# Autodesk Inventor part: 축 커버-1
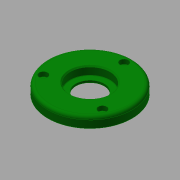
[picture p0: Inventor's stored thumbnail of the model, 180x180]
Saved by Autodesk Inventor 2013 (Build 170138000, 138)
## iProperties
Created: 2015-10
Part Number: 축 커버-1
Document SubType Name: Modeling
Designer: mdu
Density: 7.86 g/cm^3
Material: 강철, 연강
Mass: 324.903 g
Surface Area: 132.124 cm^2
Volume: 41.3362 cm^3
Author: mdu
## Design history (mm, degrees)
sketch "스케치1"
  geometry: C1 r 40 at (0, 0) reference; C2 r 26 at (0, 0) reference; 1 further point
  node "참조1"
  node "참조2"
extrude "돌출1" new body sketch "스케치1" distance "d0" = 10; taper "d1" = 0 deg
extrude "돌출2" join sketch "스케치1" distance "d2" = 3; taper "d3" = 0 deg
hole "구멍1" diameter "d6" = 27; stored, may be unused: countersink angle "d10" = 90 deg, drill point angle "d12" = 118 deg; dims "d4" = 10, "d5" = 10, "d7" = 6, "d8" = 38, "d9" = 8, "d11" = 8
sketch "스케치2"
  geometry: C1 r 20 at (0, 0); 1 further point
  constraints: 1 centre point, 1 coincident
  dimensions: "d13" = 40 diameter of C1
extrude "돌출3" cut sketch "스케치2" distance "d14" = 3; taper "d15" = 0 deg
sketch "스케치3"
  geometry: C1 r 1.621 at (0, 32.5) reference; 1 further point
hole "구멍2" sketch "스케치3" at (0, 32.5) diameter "d16" = 4.5; stored, may be unused: countersink angle "d20" = 90 deg, drill point angle "d22" = 118 deg; dims "d17" = 6, "d18" = 8, "d19" = 4.4, "d21" = 8
fillet "모깎기1" dims "d26" = 3, "d27" = 0.3
chamfer "모따기1" distance "d28" = 1; stored, may be unused: second distance "d29" = 2, angle "d30" = 45 deg
node "솔리드1"
pattern_circular "원형 패턴1" dims angle "d24" = 360 deg
node "참조3"
